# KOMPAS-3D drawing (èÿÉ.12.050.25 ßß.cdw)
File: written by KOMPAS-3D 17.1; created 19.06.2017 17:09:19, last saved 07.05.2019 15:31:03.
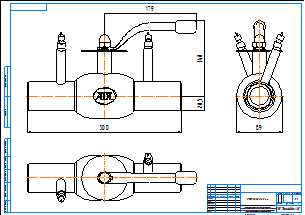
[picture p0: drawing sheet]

Sheet 1: A2, landscape

Title block, sheet 1: name: КШР.12.050.25 сс; material: Внимание! Данный продукт является объектом авторского права ООО «Торговый Дом АДЛ». / Запрещается изменение, копирование, распространение / (в том числе путем копирования на другие сайты и ресурсы в Интернете) / или любое иное использование информации и объектов без предварительного / согласия правообладателя (ООО «Торговый Дом АДЛ»).; scale: 1:1; sheets: 1; organisation: ООО "Торговый дом АДЛ"; sheet format: A2; stored path: C:\Users\tra\Desktop\2д чертежи\Шаровые краны БИВАЛ\КШР_Бивал_серия_12\KOMPAS 2D\КШР.12.050.25 сс.cdw

Views: Спереди 1, Проекционный вид 2, Проекционный вид 3
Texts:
  Klimkovich
  ADL
Dimensions and other numbers on the sheet: 300; 179; 148; 28,5; 89; 1:1; 1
